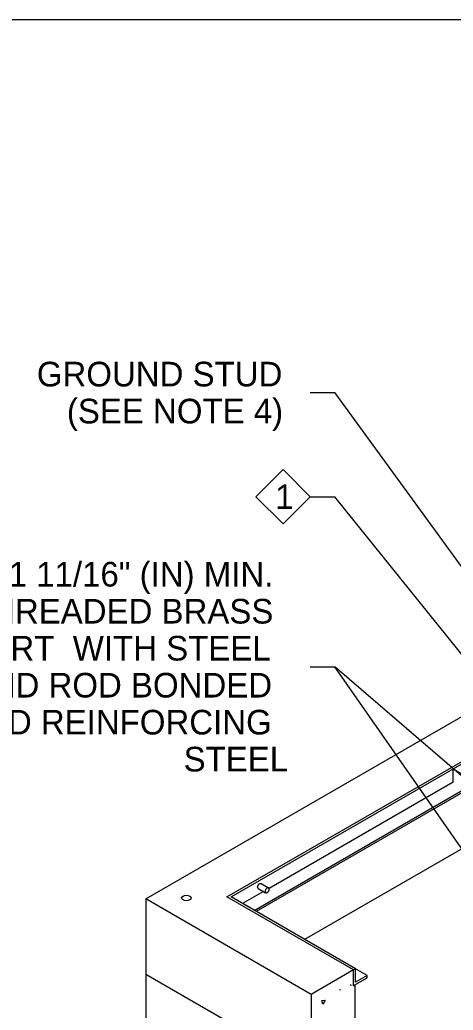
# Model space of a CAD drawing. Extents: x 99862 to 103151, y 100000 to 105076.
# Drawn here: x 101020 to 101301, y 101433 to 102076 of the extents above; entities that cross this region are included whole.
import ezdxf

# ---------------------------------------------------------------- set-up
doc = ezdxf.new("R2010")
doc.units = 0
for name, color, linetype in [('Level 1', 7, 'Continuous'), ('Level 15', 7, 'Continuous'), ('Level 2', 7, 'Continuous'), ('Level 20', 7, 'Continuous'), ('Level 3', 7, 'Continuous'), ('Level 4', 7, 'Continuous'), ('Level 5', 7, 'Continuous'), ('Level 9', 7, 'Continuous')]:
    doc.layers.add(name, color=color, linetype=linetype)

msp = doc.modelspace()

# ---------------------------------------------------------------- linework, layer by layer
at = {"layer": 'Level 1'}
msp.add_lwpolyline([(99862, 99999.5), (103151, 99999.5), (103151, 102075.5), (99862, 102075.5)], close=True, dxfattribs=at)
at = {"layer": 'Level 15'}
for p, q in [((101208.01, 101833.58), (101224.01, 101833.58)), ((101390.12, 101605.45), (101224.01, 101833.58)), ((101208.01, 101766.03), (101224.01, 101766.03)), ((101366.49, 101588.8), (101224.01, 101766.03)), ((101208.01, 101655.71), (101224.01, 101655.71)), ((101335.29, 101559.62), (101224.01, 101655.71)), ((101343.25, 101484.61), (101224.01, 101655.71))]:
    msp.add_line(p, q, dxfattribs=at)
at = {"layer": 'Level 2'}
for p, q in [((101208.75, 101394.08), (101101.51, 101456)), ((101101.51, 101456), (101101.51, 101162.06))]:
    msp.add_line(p, q, dxfattribs=at)
at = {"layer": 'Level 20'}
msp.add_lwpolyline([(101190.45, 101783.59), (101208.01, 101766.03), (101190.45, 101748.48), (101172.9, 101766.03)], close=True, dxfattribs=at)
at = {"layer": 'Level 3'}
for p, q in [((101101.51, 101504.99), (101323.59, 101633.2)), ((101154.1, 101506.26), (101325.57, 101605.26)), ((101327.78, 101549.89), (101204.48, 101478.71)), ((101101.51, 101504.99), (101101.51, 101456)), ((101208.75, 101443.07), (101101.51, 101504.99)), ((101236.15, 101458.89), (101154.1, 101506.26)), ((101236.15, 101458.89), (101208.75, 101443.07)), ((101237.48, 101459.65), (101236.15, 101458.89)), ((101236.15, 101448.68), (101236.15, 101458.89)), ((101237.48, 101450.98), (101237.48, 101459.65)), ((101237.04, 101449.19), (101244.99, 101453.79)), ((101244.99, 101455.32), (101237.48, 101450.98)), ((101244.99, 101453.79), (101244.99, 101455.32)), ((101236.15, 101448.68), (101237.04, 101449.19)), ((101237.04, 101449.19), (101237.04, 101406.33)), ((101208.75, 101443.07), (101208.75, 101394.08))]:
    msp.add_line(p, q, dxfattribs=at)
msp.add_ellipse((101127.81, 101505.62), major_axis=(-3.12, 0), ratio=0.57735, dxfattribs=at)
at = {"layer": 'Level 4'}
for p, q in [((101156.75, 101506.26), (101325.57, 101603.73)), ((101300.83, 101580.77), (101181.43, 101511.83)), ((101171.78, 101497.59), (101308.34, 101576.43)), ((101308.34, 101574.9), (101173.1, 101496.82)), ((101176.25, 101515.03), (101181.11, 101512.22)), ((101177.86, 101509.77), (101164.27, 101501.93)), ((101174.37, 101511.79), (101179.19, 101509)), ((101237.48, 101459.65), (101156.75, 101506.26)), ((101244.99, 101455.32), (101237.48, 101459.65))]:
    msp.add_line(p, q, dxfattribs=at)
for points in [[(101174.39, 101511.78), (101174.37, 101511.79), (101174.29, 101511.84), (101174.16, 101511.97), (101174.04, 101512.2), (101173.97, 101512.54), (101174, 101512.96), (101174.13, 101513.47), (101174.34, 101513.92), (101174.65, 101514.37), (101174.97, 101514.71), (101175.28, 101514.93), (101175.57, 101515.07), (101175.75, 101515.11), (101175.9, 101515.12), (101175.94, 101515.12), (101175.98, 101515.12)], [(101175.98, 101515.12), (101176.01, 101515.11), (101176.05, 101515.11), (101176.15, 101515.08), (101176.21, 101515.06), (101176.25, 101515.03)], [(101180.84, 101512.31), (101180.87, 101512.31), (101180.91, 101512.3), (101181.04, 101512.27), (101181.19, 101512.19), (101181.36, 101512), (101181.46, 101511.76), (101181.51, 101511.42), (101181.49, 101511.08), (101181.38, 101510.61), (101181.22, 101510.23), (101180.99, 101509.86), (101180.79, 101509.59), (101180.51, 101509.29), (101180.21, 101509.07), (101179.9, 101508.94), (101179.66, 101508.88), (101179.42, 101508.89), (101179.2, 101508.98), (101179.02, 101509.16), (101178.9, 101509.4), (101178.84, 101509.73), (101178.86, 101510.15), (101178.99, 101510.66), (101179.21, 101511.11), (101179.51, 101511.56), (101179.83, 101511.9), (101180.14, 101512.12), (101180.43, 101512.26), (101180.61, 101512.31), (101180.76, 101512.31), (101180.8, 101512.31), (101180.84, 101512.31)]]:
    msp.add_open_spline(points, degree=3, dxfattribs=at)
at = {"layer": 'Level 5'}
for p, q in [((101300.83, 101580.77), (101300.83, 101589.44)), ((101300.83, 101589.44), (101309.66, 101584.34))]:
    msp.add_line(p, q, dxfattribs=at)
at = {"layer": 'Level 9'}
for p, q in [((101227.09, 101446.22), (101227.72, 101446.1)), ((101234.74, 101448.65), (101234.43, 101449.46)), ((101209.63, 101443.25), (101209.52, 101443.51)), ((101208.75, 101433.02), (101208.8, 101432.99))]:
    msp.add_line(p, q, dxfattribs=at)
msp.add_lwpolyline([(101216.35, 101436.78), (101215.53, 101439.1), (101217.73, 101439.41), (101216.35, 101436.78)], dxfattribs=at)

# ---------------------------------------------------------------- texts
at = {"layer": 'Level 20'}
for s, p in [('GROUND STUD', (101030.76, 101837.58)), ('(SEE NOTE 4)', (101050.24, 101813.58)), ('1', (101185.43, 101758.04)), ('1/4-20 UNC × 1 11/16" (IN) MIN.', (100875.18, 101707.71)), ('LENGTH THREADED BRASS', (100895.29, 101683.71)), ('GROUND INSERT  WITH STEEL', (100862.68, 101659.71)), ('LEAD GROUND ROD BONDED', (100875.47, 101635.71)), ('TO FRAME AND REINFORCING', (100865.77, 101611.71)), ('STEEL', (101125.97, 101587.71))]:
    msp.add_text(s, height=16, dxfattribs=at).set_placement(p)

doc.saveas('drawing.dxf')
